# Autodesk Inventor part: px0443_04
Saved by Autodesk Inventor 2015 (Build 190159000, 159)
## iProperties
Created: 2019-05
Part Number: px0443_04
Checked By: TraceParts S.A.
Material: Generic
Catalog Web Link: www.traceparts.com
Document SubType Name: Modeling
Designer: TraceParts
Density: 1 g/cm^3
Appearance: Default
Company: TraceParts S.A.
Author: TraceParts
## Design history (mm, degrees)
feature "px0443_04.ipt"
body "Solid1"
